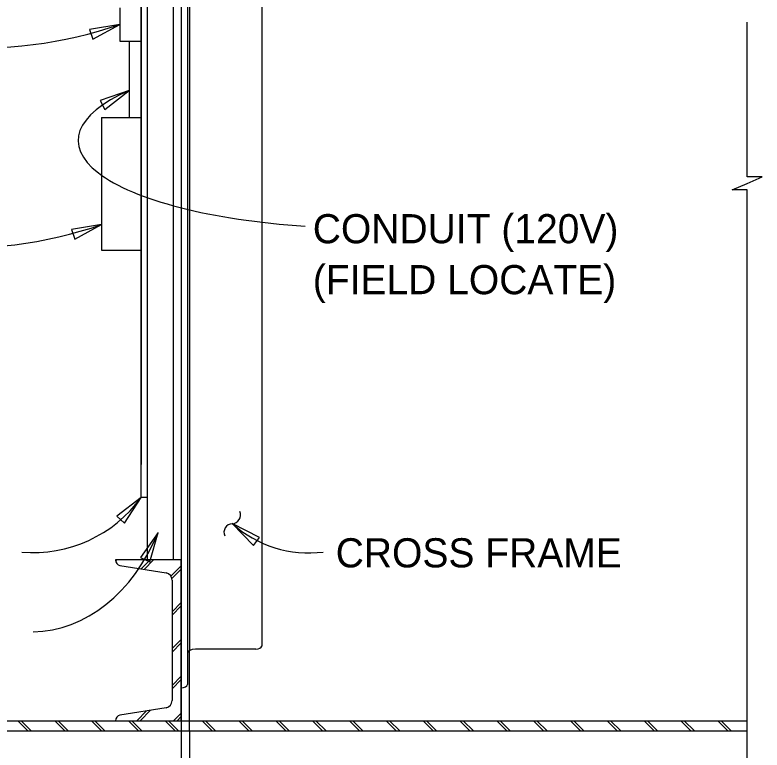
# Model space of a CAD drawing. Extents: x 927736.2 to 927809.6, y 636703.6 to 636757.7.
# Drawn here: x 927794.26 to 927803.81, y 636715.22 to 636724.62 of the extents above; entities that cross this region are included whole.
import ezdxf

# ---------------------------------------------------------------- set-up
doc = ezdxf.new("R2010")
doc.units = 0
for name, color, linetype in [('Default', 7, 'Continuous'), ('DimLines_dp', 7, 'Continuous'), ('Miscellaneous1', 7, 'Continuous'), ('Miscellaneous3', 7, 'Continuous')]:
    doc.layers.add(name, color=color, linetype=linetype)

msp = doc.modelspace()

# ---------------------------------------------------------------- linework, layer by layer
at = {"layer": 'Default'}
msp.add_line((927795.8751, 636725.1447), (927795.8751, 636718.8675), dxfattribs=at)
at = {"layer": 'DimLines_dp'}
for points in [[(927795.6025, 636724.4946), (927795.2169, 636724.431), (927795.2593, 636724.3076)], [(927795.7209, 636723.648), (927795.3505, 636723.5234), (927795.4122, 636723.4084)], [(927795.3704, 636721.9351), (927794.9849, 636721.8715), (927795.0273, 636721.7481)], [(927795.8751, 636718.4463), (927795.566, 636718.2072), (927795.662, 636718.1187)], [(927797.0406, 636718.111), (927797.3117, 636717.8296), (927797.3893, 636717.9346)], [(927796.0911, 636717.9989), (927795.8675, 636717.6785), (927795.9855, 636717.6227)]]:
    msp.add_lwpolyline(points, close=True, dxfattribs=at)
msp.add_lwpolyline([(927803.6221, 636713.104), (927803.6221, 636722.3779), (927803.431, 636722.3779), (927803.6221, 636722.4611), (927803.8133, 636722.5444), (927803.6221, 636722.5444), (927803.6221, 636724.5258)], dxfattribs=at)
for centre, radius, start, end in [((927793.8016, 636729.7326), 5.5389, 265.3641, 288.97308), ((927793.5696, 636727.1731), 5.5389, 265.3641, 288.97308), ((927794.4954, 636719.4432), 1.7022, 265.09847, 324.1488), ((927797.0352, 636718.2201), 0.1103, 272.35831, 24.08553), ((927797.0443, 636717.9998), 0.1103, 92.35831, 204.08553), ((927798.0223, 636719.2082), 1.4723, 228.179, 277.09313)]:
    msp.add_arc(centre, radius, start, end, dxfattribs=at)
for centre, major_axis, ratio, start_param, end_param in [((927798.6968, 636723.0101), (3.6273, 0), 0.307602, 2.532927, 4.511363), ((927794.459, 636719.1661), (-0.0364, 2.4376), 0.759061, 3.141594, 4.201813)]:
    msp.add_ellipse(centre, major_axis=major_axis, ratio=ratio, start_param=start_param, end_param=end_param, dxfattribs=at)
at = {"layer": 'Miscellaneous1'}
for p, q in [((927795.6023, 636724.7065), (927795.6023, 636724.2826)), ((927795.6023, 636724.2826), (927795.8751, 636724.2826)), ((927795.7209, 636724.2826), (927795.7209, 636723.3025)), ((927795.8751, 636723.3025), (927795.8751, 636724.2826)), ((927795.3703, 636723.3025), (927795.8751, 636723.3025)), ((927795.3703, 636723.3025), (927795.3703, 636721.6066)), ((927795.3703, 636721.6066), (927795.8751, 636721.6066))]:
    msp.add_line(p, q, dxfattribs=at)
at = {"layer": 'Miscellaneous3'}
for p, q in [((927796.286, 636728.5919), (927796.286, 636717.6461)), ((927796.4917, 636728.5589), (927796.4917, 636716.4866)), ((927797.4166, 636728.5589), (927797.4166, 636716.5445)), ((927796.4659, 636728.0669), (927796.4659, 636716.0519)), ((927796.3888, 636727.6412), (927796.3888, 636715.5906)), ((927795.952, 636718.4462), (927795.952, 636717.6461)), ((927796.3888, 636717.6461), (927795.546, 636717.6461)), ((927795.5502, 636717.6321), (927795.5642, 636717.6461)), ((927795.6049, 636717.5765), (927796.1934, 636717.4803)), ((927795.8775, 636717.532), (927795.9916, 636717.6461)), ((927795.9149, 636717.5258), (927796.0352, 636717.6461)), ((927796.2537, 636717.4373), (927796.3888, 636717.5723)), ((927796.3888, 636715.5905), (927796.3888, 636717.6461)), ((927796.2671, 636717.4071), (927796.3888, 636717.5287)), ((927796.2706, 636717.3891), (927796.2706, 636715.8474)), ((927796.2706, 636716.9832), (927796.3888, 636717.1014)), ((927796.2706, 636716.9396), (927796.3888, 636717.0578)), ((927796.2706, 636716.5123), (927796.3888, 636716.6305)), ((927796.2706, 636716.4687), (927796.3888, 636716.5869)), ((927796.4917, 636715.5906), (927796.4917, 636716.4866)), ((927797.3395, 636716.5046), (927796.5687, 636716.5046)), ((927796.2706, 636716.0414), (927796.3888, 636716.1595)), ((927796.2706, 636715.9977), (927796.3888, 636716.1159)), ((927796.1934, 636715.7562), (927795.6049, 636715.6601)), ((927795.8197, 636715.5905), (927795.9449, 636715.7156)), ((927795.8633, 636715.5905), (927795.997, 636715.7241)), ((927796.2907, 636715.5905), (927796.3888, 636715.6886)), ((927786.3327, 636715.5906), (927803.6221, 636715.5906)), ((927794.4275, 636715.462), (927794.2989, 636715.5906)), ((927794.4711, 636715.462), (927794.3425, 636715.5906)), ((927794.8985, 636715.462), (927794.7699, 636715.5906)), ((927794.9421, 636715.462), (927794.8135, 636715.5906)), ((927795.3694, 636715.462), (927795.2408, 636715.5906)), ((927795.413, 636715.462), (927795.2844, 636715.5906)), ((927795.546, 636715.5905), (927796.3888, 636715.5905)), ((927795.8403, 636715.462), (927795.7117, 636715.5906)), ((927795.8839, 636715.462), (927795.7553, 636715.5906)), ((927796.3113, 636715.462), (927796.1827, 636715.5906)), ((927796.3549, 636715.462), (927796.2263, 636715.5906)), ((927796.3343, 636715.5905), (927796.3888, 636715.645)), ((927796.3888, 636715.5906), (927796.3888, 636715.462)), ((927796.4917, 636715.462), (927796.4917, 636715.5906)), ((927796.7822, 636715.462), (927796.6536, 636715.5906)), ((927796.8258, 636715.462), (927796.6972, 636715.5906)), ((927797.2531, 636715.462), (927797.1245, 636715.5906)), ((927797.2967, 636715.462), (927797.1681, 636715.5906)), ((927797.7241, 636715.462), (927797.5955, 636715.5906)), ((927797.7677, 636715.462), (927797.6391, 636715.5906)), ((927798.195, 636715.462), (927798.0664, 636715.5906)), ((927798.2386, 636715.462), (927798.11, 636715.5906)), ((927798.6659, 636715.462), (927798.5373, 636715.5906)), ((927798.7095, 636715.462), (927798.5809, 636715.5906)), ((927799.1369, 636715.462), (927799.0083, 636715.5906)), ((927799.1805, 636715.462), (927799.0519, 636715.5906)), ((927799.6078, 636715.462), (927799.4792, 636715.5906)), ((927799.6514, 636715.462), (927799.5228, 636715.5906)), ((927800.0787, 636715.462), (927799.9501, 636715.5906)), ((927800.1223, 636715.462), (927799.9937, 636715.5906)), ((927800.5497, 636715.462), (927800.4211, 636715.5906)), ((927800.5933, 636715.462), (927800.4647, 636715.5906)), ((927801.0206, 636715.462), (927800.892, 636715.5906)), ((927801.0642, 636715.462), (927800.9356, 636715.5906)), ((927801.4916, 636715.462), (927801.363, 636715.5906)), ((927801.5352, 636715.462), (927801.4066, 636715.5906)), ((927801.9625, 636715.462), (927801.8339, 636715.5906)), ((927802.0061, 636715.462), (927801.8775, 636715.5906)), ((927802.4334, 636715.4621), (927802.3048, 636715.5906)), ((927802.477, 636715.4621), (927802.3484, 636715.5906)), ((927802.9044, 636715.4621), (927802.7758, 636715.5907)), ((927802.948, 636715.4621), (927802.8194, 636715.5907)), ((927803.3753, 636715.4621), (927803.2467, 636715.5907)), ((927803.4189, 636715.4621), (927803.2903, 636715.5907)), ((927786.3327, 636715.462), (927803.6221, 636715.462)), ((927796.3888, 636715.462), (927796.3888, 636713.6123)), ((927796.4917, 636715.462), (927796.4917, 636713.6123))]:
    msp.add_line(p, q, dxfattribs=at)
msp.add_lwpolyline([(927795.8751, 636726.4629), (927795.952, 636726.4629), (927795.952, 636718.4462), (927795.8751, 636718.4462)], close=True, dxfattribs=at)
for centre, radius, start, end in [((927795.6165, 636717.6461), 0.0705, 180, 260.5), ((927796.1781, 636717.3891), 0.0925, 360, 80.5), ((927796.1781, 636715.8474), 0.0925, 279.5, 360), ((927795.6165, 636715.5905), 0.0705, 99.5, 180)]:
    msp.add_arc(centre, radius, start, end, dxfattribs=at)
for centre, major_axis, end_param in [((927797.3395, 636716.5445), (0.0771, 0), 6.283185), ((927796.5687, 636716.4514), (-0.1028, 0), 6.283185), ((927796.3888, 636716.0524), (0.0771, 0), 6.270045)]:
    msp.add_ellipse(centre, major_axis=major_axis, ratio=0.5176, start_param=4.712389, end_param=end_param, dxfattribs=at)

# ---------------------------------------------------------------- texts
at = {"layer": 'DimLines_dp'}
for s, p in [('CONDUIT (120V)', (927798.0696, 636721.6959)), ('(FIELD LOCATE)', (927798.0696, 636721.0447)), ('CROSS FRAME', (927798.3625, 636717.551))]:
    msp.add_text(s, height=0.372961, dxfattribs=at).set_placement(p)

doc.saveas('drawing.dxf')
